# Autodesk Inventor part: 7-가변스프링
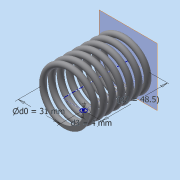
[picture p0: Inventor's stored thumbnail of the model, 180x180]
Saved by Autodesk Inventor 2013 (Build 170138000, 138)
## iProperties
Created: 2014-12
Part Number: 7-가변스프링
Material: 일반
Document SubType Name: Modeling
Designer: WINDOWS7
Density: 1 g/cm^3
Author: WINDOWS7
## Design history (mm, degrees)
sketch "스케치1"
  geometry: L1 (0, 0)-(15.5, 0); L2 (15.5, 0)-(15.5, 48.5); L3 (15.5, 48.5)-(0, 48.5); L4 (0, 48.5)-(0, 0); C1 r 2 at (15.5, 0)
  constraints: 8 end point, 2 parallel, 1 centre point, 1 coincident, 1 horizontal, 1 perpendicular
  dimensions: "d0" = 31 diameter of L2 L4; "d2" = 48.5 distance between parallel lines of L3 L1 (derived); "d3" = 4 diameter of C1
feature "코일1" pitch "d4" = 10; turns "d6" = 7.5; dims "d5" = 48.5 (= d2), "d7" = 0, angle "d8" = 90 deg, angle "d9" = 90 deg, "d10" = 0, "d11" = 0
node "작업 평면1"
sketch "스케치2"
  geometry: L1 (-17.5, 0)-(-13.5, 0) reference; 1 further point
  constraints: 1 horizontal alignment
extrude "돌출1" cut sketch "스케치2" distance "d13" = 10; taper "d14" = 0 deg
node "작업 평면2"
sketch "스케치3"
  geometry: L1 (13.5, 0)-(17.5, 0) reference; 1 further point
  constraints: 1 horizontal alignment
extrude "돌출2" cut sketch "스케치3" distance "d16" = 10; taper "d17" = 0 deg
node "솔리드1"
node "절단 모서리 투영1"
node "절단 모서리 투영2"
other parameters: "d12" = 0, "d15" = 48.5 (= d2)
